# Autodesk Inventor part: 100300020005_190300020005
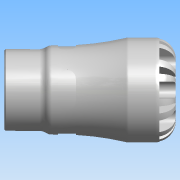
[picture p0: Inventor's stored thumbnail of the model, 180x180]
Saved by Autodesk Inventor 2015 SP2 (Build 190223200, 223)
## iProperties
Created: 2016-12
Part Number: 100300020005_190300020005
Material: PVC-Piping
Description: PLASSON FEMALE ADAPTOR 20X1/2" SERIES 1
Document SubType Name: Modeling
Designer: KIM
Mass: 664.223 g
Surface Area: 733.008 cm^2
Volume: 474.445 cm^3
Density: 1.4 g/cm^3
Appearance: Smooth - White
Author: KIM
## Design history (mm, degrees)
derived "1003.ipt"
feature "Solid1::1003.ipt"
tag "TaggingFeature1"
body "Solid1"
other parameters: "d0" = 67, "d1" = 18.9, "d3" = 25, "d4" = 41, "d6" = 45, "d8" = 34.85, "d13" = 6.4, "d14" = 6.4, "d15" = 0, "d17" = 360 deg, "d19" = 8 deg, "d20" = 0.4, "d21" = 0.4, "d22" = 8 deg, "d24" = 0, "d26" = 360 deg, "d32" = 4.1, "d33" = 4.1, "d39" = 0.55893, "d42" = 18.631, "d43" = 31.98, "d46" = 1.66667, "d47" = 17, "d48" = 17.69945, "d50" = 1.65, "d51" = 0.41, "d54" = 7, "d55" = 4.4, "d57" = 12.544, "d58" = 0, "d68" = 360 deg, "d72" = 0.4, "d74" = 0, "d76" = 5.95, "E_" = 41, "H_" = 67, "l_" = 45, "Rp" = 18.631, "l_2" = 17, "d9" = 8, "d11" = 41, "d12" = 25, "d49" = 5
